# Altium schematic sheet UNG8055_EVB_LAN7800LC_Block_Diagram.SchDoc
size 416 x 264 mm; DocumentNumber: 1; SheetNumber: 1; SheetTotal: 2; PageTitle: Block Diagram; PageSetup: Record=PageOptions¦CenterHorizontal=True¦CenterVertical=True¦PrintScale=1.02¦XCorrection=1.00¦YCorrection=1.00¦PrintKind=0¦BorderSize=5000000¦LeftOffset=0¦BottomOffset=0¦Orientation=2¦PaperLength=1000¦PaperWidth=1000¦Scale=100¦PaperSource=7¦PrintQuality=-3¦MediaType=1¦DitherType=10¦PrintScaleMode=1¦PaperKind=11 x 17¦PaperIndex=119
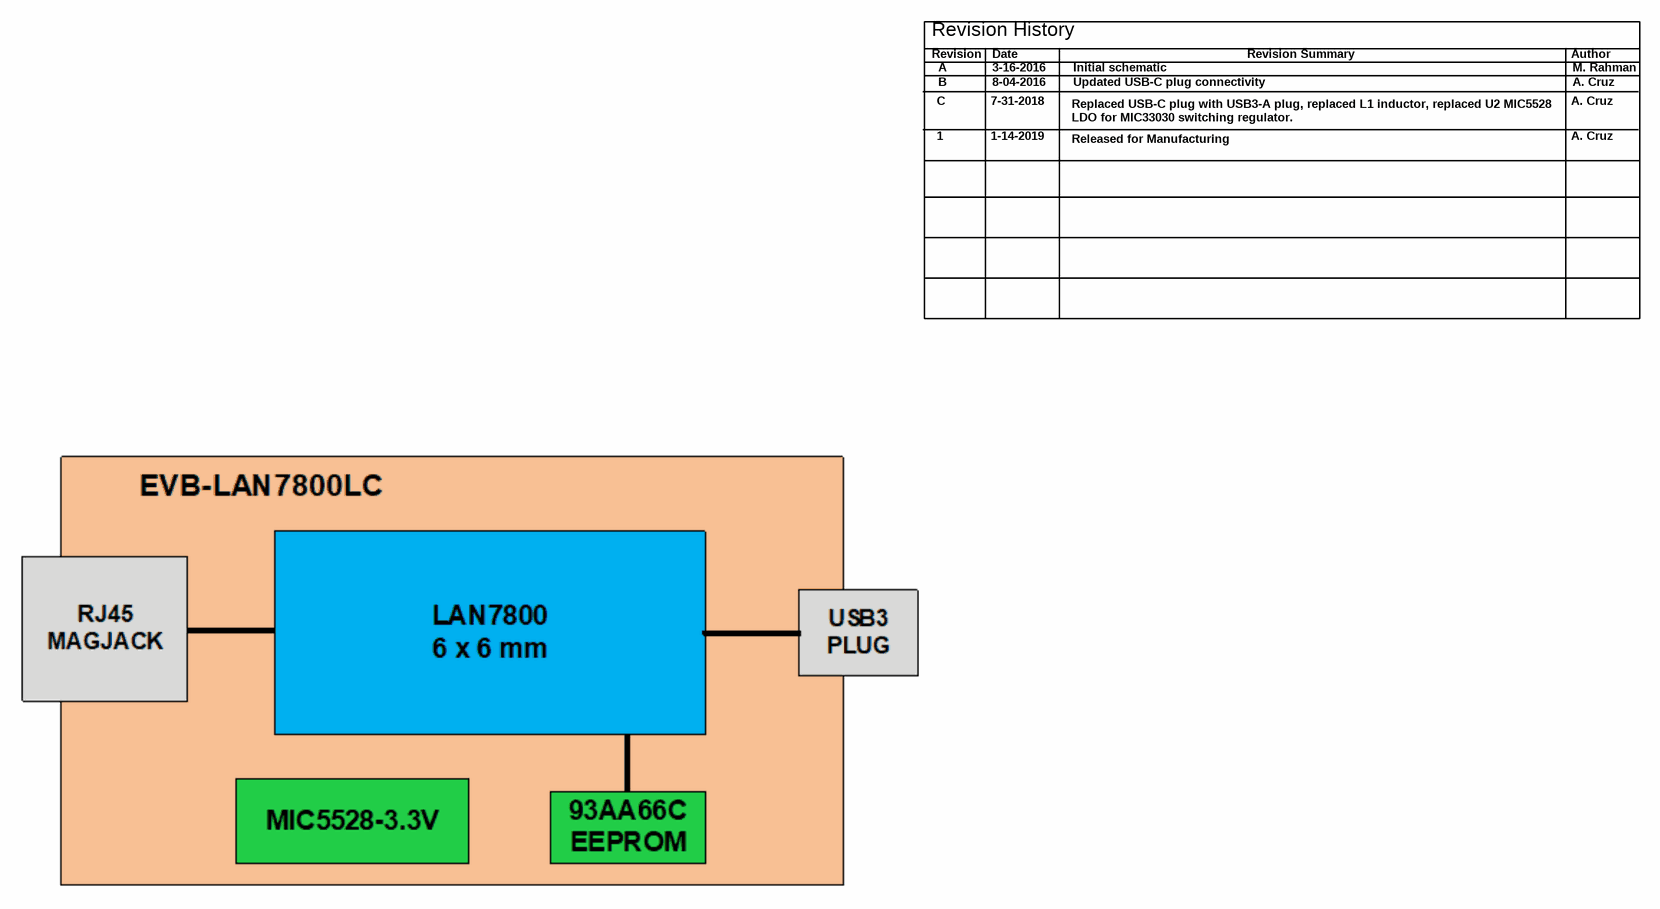
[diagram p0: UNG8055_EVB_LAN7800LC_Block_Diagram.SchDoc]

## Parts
?  (no value)  (graphical)

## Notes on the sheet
- Revision History
- Revision
- C
- A
- B
- 7-31-2018
- Date
- 3-16-2016
- 8-04-2016
- Initial schematic
- Updated USB-C plug connectivity
- Revision Summary
- Author
- A. Cruz
- M. Rahman
- 1
- 1-14-2019
- Replaced USB-C plug with USB3-A plug, replaced L1 inductor, replaced U2 MIC5528 LDO for MIC33030 switching regulator.
- Released for Manufacturing

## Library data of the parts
? = Title Block B_UNG1_Altium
